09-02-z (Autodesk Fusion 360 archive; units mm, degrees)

design "09-02-z" references "09-02-KOTEI", "09-02-KADOU"
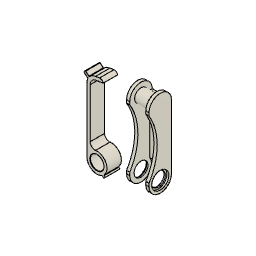
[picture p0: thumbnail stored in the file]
component_insert "コンポーネントの挿入1"
ground "固定1"
component_insert "コンポーネントの挿入3"
ground "固定4"

design "09-02-KADOU"
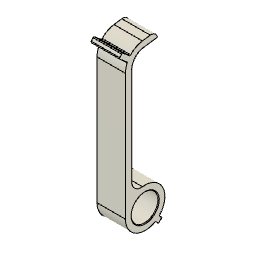
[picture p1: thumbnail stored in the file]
sketch "スケッチ1" plane through (0, 0, 0) normal (1, 0, 0) x axis (0, 0, -1)
  circle C1 centre (0, 0) radius 6.25
  point P1 (0, 0)
  point P2 (0, 0)
  coincident P1 P2
  dimension "d1" diameter C1 = 12.5
extrude "押し出し1" new body sketch "スケッチ1" distance 9
sketch "スケッチ2" plane through (0, 0, 0) normal (1, 0, 0) x axis (0, 0, -1)
  line L1 (-4.25, 0) -> (-4.25, 40)
  line L2 (-6.25, 0) -> (-4.25, 0)
  line L3 (-6.25, 40) -> (-6.25, 0)
  line L4 (3.8647, 44.8349) -> (-0.5915, 44.2086)
  line L5 (3.5864, 46.8155) -> (3.8647, 44.8349)
  line L6 (-0.8698, 46.1892) -> (3.5864, 46.8155)
  circle C1 centre (0, 0) radius 6.25
  arc A1 centre (0, 40) radius 4.25 clockwise from (-4.25, 40) to (-0.5915, 44.2086)
  arc A2 centre (0, 40) radius 6.25 clockwise from (-6.25, 40) to (-0.8698, 46.1892)
  point P1 (0, 0)
  point P8 (0, 40)
  point P12 (0, 40)
  vertical L1
  horizontal L2
  vertical L3
  coincident P1 L2
  tangent L3 C1
  perpendicular L4 L5
  perpendicular L5 L6
  coincident P8 P12
  vertical P1 P8
  tangent L1 A1
  tangent A1 L4
  tangent L3 A2
  dimension "d5" distance L1 L3 = 2
  dimension "d18" distance L4 L6 = 2
  dimension "d21" distance P8 L5 = 4.5
  dimension "d22" angle L1 L4 = 98
  dimension "d54" distance P1 P12 = 40
extrude "押し出し2" add sketch "スケッチ2" profile of L1 L3 C1 distance 9
sketch "スケッチ4" plane through (0, 0, 0) normal (1, 0, 0) x axis (0, 0, -1)
  line L1 (5.3033, -5.3033) -> (0, 0)
  line L2 (4.2426, -6.364) -> (5.3033, -5.3033)
  line L3 (-1.0607, -1.0607) -> (4.2426, -6.364)
  line L4 (0, 0) -> (-1.0607, -1.0607)
  line L5 (-22.5, 0) -> (-1.75, 0)
  point P1 (0, 0)
  point P2 (0, 0)
  perpendicular L1 L2
  parallel L1 L3
  parallel L2 L4
  coincident P1 P2
  dimension "d24" angle L1 L5 = 45
  dimension "d25" distance L2 L4 = 7.5
  dimension "d26" distance L1 L3 = 1.5
extrude "押し出し4" add sketch "スケッチ4" profile of L1 L2 L3 L4 distance 9
joint_origin "JointOrigin1" OffsetX 0 OffsetY 0 OffsetZ 0 AngleZ 0
sketch "スケッチ5" plane through (0, 0, 0) normal (1, 0, 0) x axis (0, 0, -1)
  line L1 (0, 40) -> (-7.2774, 46.1065)
  line L2 (-0.9642, 38.8509) -> (0, 40)
  line L3 (-8.2416, 44.9574) -> (-0.9642, 38.8509)
  line L4 (-7.2774, 46.1065) -> (-8.2416, 44.9574)
  line L5 (0, 22.5) -> (0, 1.75)
  arc A1 centre (0, 40) radius 4.25 clockwise from (-4.25, 40) to (-0.5915, 44.2086)
  point P3 (0, 40)
  point P8 (0, 40)
  perpendicular L1 L2
  parallel L1 L3
  parallel L2 L4
  coincident P3 P8
  dimension "d33" angle L1 L5 = 50
  dimension "d34" distance L1 L3 = 1.5
  dimension "d35" distance L2 L4 = 9.5
extrude "押し出し5" add sketch "スケッチ5" profile of L1 L3 L4 A1 distance 9
fillet "フィレット3" radius 2
sketch "スケッチ6" plane through (0, 43.4339, 6.1042) normal (0, -0.9903, -0.1392) x axis (-1, 0, 0)
  line L1 (-4.5, 10.0669) -> (4.5, 10.0669)
  line L2 (-4.5, 5.5669) -> (-4.5, 10.0669)
  line L3 (4.5, 5.5669) -> (-4.5, 5.5669)
  line L4 (4.5, 10.0669) -> (4.5, 5.5669)
  circle C1 centre (0, 8.0669) radius 0.75
  point P1 (0, 0)
  point P6 (0, 8.0669)
  vertical P1 P6
  dimension "d40" distance L1 P6 = 2
  dimension "d41" diameter C1 = 1.5
extrude "押し出し6" add sketch "スケッチ6" profile of C1 along normal blind 0.7
fillet "フィレット4" radius 0.6
fillet "フィレット5" radius 3
fillet "フィレット6" radius 0.3
hole "穴" HoleDepth 9 HoleDiameter 8.5 TipAngle 118
chamfer "面取り" distance 0.2

design "09-02-KOTEI"
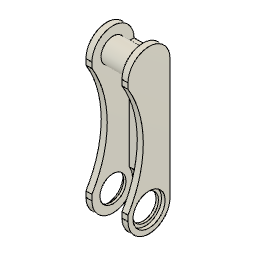
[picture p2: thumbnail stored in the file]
sketch "スケッチ1" plane through (0, 0, 0) normal (1, 0, 0) x axis (0, 0, -1)
  circle C1 centre (0, 40) radius 4
  point P1 (0, 0)
  point P2 (0, 40)
  vertical P1 P2
  dimension "d1" diameter C1 = 8
  dimension "d29" distance P1 P2 = 40
extrude "押し出し1" new body sketch "スケッチ1" + "スケッチ5" profile of S1:C1 distance 10
sketch "スケッチ2" plane through (5, 0, 0) normal (1, 0, 0) x axis (0, 0, -1)
  line L1 (-7, 0) -> (-7, 40)
  line L2 (7, 40) -> (7, 0)
  line L3 (0, 0) -> (0, 40)
  circle C1 centre (0, 40) radius 4
  arc A1 centre (0, 0) radius 7 clockwise from (7, 0) to (-7, 0)
  arc A2 centre (0, 40) radius 7 clockwise from (-7, 40) to (7, 40)
  point P7 (0, 40)
  point P9 (0, 40)
  point P8 (0, 0)
  tangent L1 A1
  tangent A1 L2
  parallel L1 L2
  tangent L2 A2
  tangent L1 A2
  vertical L3
  coincident P7 P9
  concentric C1 A2
  dimension "d4" radius A2 = 7
  dimension "d5" distance P7 P8 = 40
extrude "押し出し2" add sketch "スケッチ2" profile of C1 L1 A1 L2 A2 along normal blind 2
mirror "ミラー" sketch "スケッチ5" mirrorStitchTolerance 0.1
sketch "スケッチ3" plane through (0, 0, 0) normal (1, 0, 0) x axis (0, 0, -1)
  line L1 (7, 40) -> (5.4, 40)
  line L2 (7, 0) -> (7, 40)
  line L3 (5.4, 0) -> (7, 0)
  line L4 (5.4, 40) -> (5.4, 0)
  point P3 (7, 40)
  point P6 (7, 40)
  point P4 (7, 0)
  point P7 (7, 0)
  horizontal L1
  vertical L2
  horizontal L3
  vertical L4
  coincident P3 P6
  coincident P4 P7
  dimension "d10" distance L2 L4 = 1.6
extrude "押し出し3" add sketch "スケッチ3" distance 10
sketch "スケッチ4" plane through (0, 0, 0) normal (1, 0, 0) x axis (0, 0, -1)
  circle C1 centre (-36.9324, 20) radius 35
  arc A1 centre (0, 40) radius 7 clockwise from (-7, 40) to (7, 40)
  arc A2 centre (0, 0) radius 7 clockwise from (7, 0) to (-7, 0)
  tangent C1 A1
  tangent C1 A2
  dimension "d13" diameter C1 = 70
extrude "押し出し4" cut sketch "スケッチ4" profile of C1 no distance stored
sketch "スケッチ5" plane through (0, 0, 0) normal (1, 0, 0) x axis (0, 0, -1)
  circle C1 centre (0, 0) radius 6.5
  arc A1 centre (0, 0) radius 7 clockwise from (7, 0) to (-7, 0)
  concentric C1 A1
  dimension "d15" diameter C1 = 13
extrude "押し出し5" cut sketch "スケッチ5" profile of C1 distance 10
chamfer "面取り" distance 0.2
hole "穴1" HoleDepth 2 HoleDiameter 8.7 TipAngle 118 CBDepth 1.2 CBDiameter 10.7
hole "穴2" HoleDepth 2 HoleDiameter 8.7 TipAngle 118 CBDepth 1.2 CBDiameter 10.7
joint_origin "JointOrigin1" sketch "スケッチ5" OffsetX 0 OffsetY 0 OffsetZ 0 AngleZ 0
